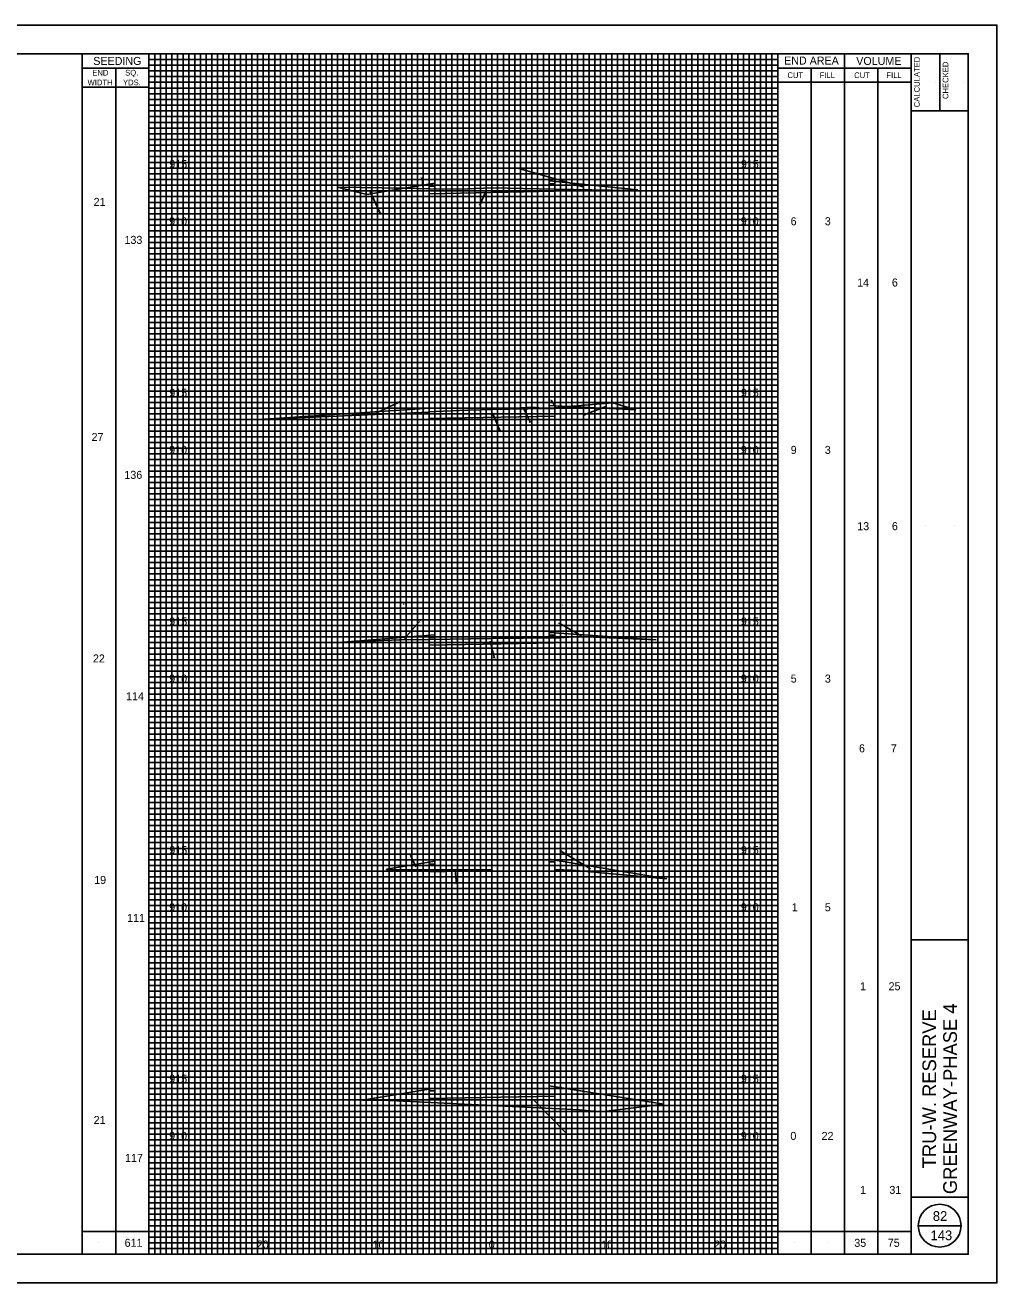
# Model space of a CAD drawing. Extents: x -73 to 160, y -2 to 1877.
# Drawn here: x 75 to 160, y 917.5 to 1027.5 of the extents above; entities that cross this region are included whole.
import ezdxf

# ---------------------------------------------------------------- set-up
doc = ezdxf.new("R2010")
doc.units = 0
for name, color, linetype in [('DR_P_Flood_Boundary', 7, 'Continuous'), ('GK_Cells', 7, 'Continuous'), ('RD_X_Fence', 7, 'Continuous'), ('TX_X_5', 7, 'Continuous'), ('UT_P_Water_Cells', 7, 'Continuous'), ('XS_P_Pavt_Layers', 7, 'Continuous'), ('XS_P_Pavt_Surface', 7, 'Continuous'), ('XS_X_Ground_Line', 7, 'Continuous')]:
    doc.layers.add(name, color=color, linetype=linetype)

msp = doc.modelspace()

# ---------------------------------------------------------------- linework, layer by layer
at = {"layer": 'DR_P_Flood_Boundary'}
for p, q in [((90.83, 920), (90.83, 1025)), ((95.83, 920), (95.83, 1025)), ((100.83, 920), (100.83, 1025)), ((105.83, 920), (105.83, 1025)), ((110.83, 920), (110.83, 1025)), ((115.83, 920), (115.83, 1025)), ((120.83, 920), (120.83, 1025)), ((125.83, 920), (125.83, 1025)), ((130.83, 920), (130.83, 1025)), ((135.83, 920), (135.83, 1025)), ((85.83, 1020), (140.83, 1020)), ((85.83, 1015), (140.83, 1015)), ((85.83, 1010), (140.83, 1010)), ((85.83, 1005), (140.83, 1005)), ((85.83, 1000), (140.83, 1000)), ((85.83, 995), (140.83, 995)), ((85.83, 990), (140.83, 990)), ((85.83, 985), (140.83, 985)), ((85.83, 980), (140.83, 980)), ((85.83, 975), (140.83, 975)), ((85.83, 970), (140.83, 970)), ((85.83, 965), (140.83, 965)), ((85.83, 960), (140.83, 960)), ((85.83, 955), (140.83, 955)), ((85.83, 950), (140.83, 950)), ((85.83, 945), (140.83, 945)), ((85.83, 940), (140.83, 940)), ((85.83, 935), (140.83, 935)), ((85.83, 930), (140.83, 930)), ((85.83, 925), (140.83, 925))]:
    msp.add_line(p, q, dxfattribs=at)
at = {"layer": 'GK_Cells'}
for p, q in [((152.5, 920), (152.5, 1025)), ((155, 1025), (155, 1020)), ((152.5, 1020), (157.5, 1020)), ((152.5, 947.5), (157.5, 947.5)), ((152.5, 925), (157.5, 925))]:
    msp.add_line(p, q, dxfattribs=at)
msp.add_lwpolyline([(0, 1025), (157.5, 1025), (157.5, 920), (0, 920)], close=True, dxfattribs=at)
at = {"layer": 'RD_X_Fence'}
for p, q in [((123.82, 1013.35), (118.29, 1014.94)), ((102.31, 1013.33), (104.88, 1012.69)), ((108.15, 1013.23), (102.31, 1013.33)), ((104.88, 1012.69), (108.15, 1013.23)), ((110.83, 1013.68), (108.15, 1013.23)), ((108.15, 1013.23), (110.33, 1013.19)), ((109.8, 1013.38), (109.72, 1014.17)), ((110.33, 1013.42), (110.83, 1013.43)), ((110.33, 1013.19), (110.33, 1013.42)), ((110.33, 1013.19), (110.33, 1012.75)), ((128.6, 1013.09), (120.83, 1013.88)), ((120.83, 1013.88), (120.83, 1013.77)), ((120.83, 1013.77), (120.83, 1013.63)), ((120.83, 1013.63), (121.33, 1013.64)), ((121.33, 1013.64), (121.33, 1013.16)), ((121.33, 1012.97), (121.33, 1013.16)), ((121.33, 1013.16), (127.83, 1013.04)), ((105.11, 1013.08), (106.05, 1011.06)), ((110.33, 1012.75), (121.33, 1012.97)), ((115.33, 1013.03), (114.78, 1011.77)), ((127.83, 1013.04), (128.6, 1013.09)), ((105.69, 993.57), (107.79, 994.55)), ((121.41, 994.12), (121, 994.71)), ((110.83, 994.02), (95.49, 993.02)), ((95.49, 993.02), (110.34, 993.64)), ((110.33, 993.68), (110.33, 993.09)), ((110.33, 993.09), (121.33, 993.31)), ((110.34, 993.68), (110.84, 993.7)), ((110.34, 993.64), (110.34, 993.68)), ((110.83, 993.92), (110.83, 994.02)), ((110.84, 993.7), (110.83, 993.92)), ((110.83, 993.92), (110.83, 993.92)), ((119.36, 994.09), (115.83, 993.87)), ((115.83, 993.87), (120.55, 993.96)), ((115.92, 993.53), (116.51, 992.04)), ((118.58, 993.97), (119.22, 992.76)), ((120.55, 993.96), (119.36, 994.09)), ((122.56, 994.14), (120.83, 994.22)), ((121.33, 993.31), (121.33, 993.98)), ((122.56, 994.14), (128.41, 993.86)), ((125.79, 994.15), (123.89, 993.41)), ((108.19, 973.86), (109.51, 975.34)), ((123.67, 974.08), (121.72, 975.2)), ((110.83, 974.19), (102.83, 973.54)), ((110.33, 973.93), (110.83, 973.94)), ((110.33, 973.77), (110.33, 973.93)), ((110.33, 973.77), (110.33, 973.26)), ((115.68, 973.61), (116.06, 972.15)), ((130.21, 973.75), (120.83, 974.39)), ((120.83, 974.39), (120.83, 974.29)), ((120.83, 974.29), (120.83, 974.14)), ((120.83, 974.14), (121.33, 974.15)), ((121.33, 974.15), (121.33, 973.92)), ((121.33, 973.48), (121.33, 973.92)), ((121.33, 973.92), (121.79, 973.92)), ((110.33, 973.26), (121.33, 973.48)), ((109.17, 953.88), (108.7, 954.9)), ((124.46, 953.71), (121.86, 955.25)), ((110.83, 954.37), (106.62, 953.67)), ((110.33, 954.11), (110.83, 954.12)), ((110.33, 953.65), (110.33, 954.11)), ((131.13, 952.85), (120.83, 954.57)), ((120.83, 954.32), (121.33, 954.33)), ((121.33, 954.33), (121.33, 953.66)), ((106.62, 953.64), (110.33, 953.61)), ((115.85, 953.62), (110.33, 953.65)), ((110.33, 953.65), (110.33, 953.44)), ((110.33, 953.44), (115.85, 953.55)), ((112.63, 953.56), (112.72, 952.41)), ((110.83, 934.54), (104.51, 933.49)), ((110.33, 934.28), (110.83, 934.29)), ((110.33, 933.61), (110.33, 934.28)), ((130.86, 933.13), (120.83, 934.74)), ((120.83, 934.49), (121.33, 934.5)), ((121.33, 934.5), (121.33, 933.83)), ((121.33, 933.83), (110.33, 933.61)), ((119.53, 933.44), (122.42, 930.49))]:
    msp.add_line(p, q, dxfattribs=at)
for points in [[(121.33, 1013.16), (115.83, 1013.27), (113.03, 1013.15), (110.33, 1013.19)], [(110.83, 1013.43), (110.83, 1013.57), (110.83, 1013.68)], [(128.41, 993.86), (126.4, 994.47), (125.69, 994.41), (122.56, 994.14)], [(113.72, 993.83), (110.84, 993.7), (110.34, 993.68), (110.33, 993.68)], [(110.83, 993.92), (110.83, 993.92)], [(121.33, 993.98), (120.83, 993.97), (120.55, 993.96), (115.83, 993.87), (113.72, 993.83)], [(120.83, 994.22), (120.83, 994.12), (120.83, 993.99)], [(120.83, 993.99), (121.33, 994.03), (122.56, 994.14)], [(102.83, 973.54), (107.75, 973.74), (110.33, 973.77)], [(121.33, 973.92), (115.83, 973.85), (110.33, 973.77)], [(110.83, 973.94), (110.83, 974.09), (110.83, 974.19)], [(121.79, 973.92), (123.34, 974.03), (130.21, 973.75)], [(110.83, 954.12), (110.83, 954.27), (110.83, 954.37)], [(120.83, 954.57), (120.83, 954.47), (120.83, 954.32)], [(106.62, 953.67), (106.62, 953.64)], [(110.33, 953.61), (110.33, 953.65)], [(115.85, 953.55), (115.85, 953.62)], [(121.33, 953.66), (121.33, 953.66)], [(121.33, 953.66), (122.86, 953.6), (131.13, 952.85)], [(110.83, 934.29), (110.83, 934.44), (110.83, 934.54)], [(120.83, 934.74), (120.83, 934.64), (120.83, 934.49)], [(104.51, 933.49), (106.31, 933.48), (115.83, 933.01), (123.48, 932.64), (125.36, 932.47), (130.86, 933.13)]]:
    msp.add_lwpolyline(points, dxfattribs=at)
at = {"layer": 'TX_X_5'}
msp.add_lwpolyline([(-10, 917.5), (160, 917.5), (160, 1027.5), (-10, 1027.5)], close=True, dxfattribs=at)
at = {"layer": 'UT_P_Water_Cells'}
for p, q in [((85.83, 1024.5), (140.83, 1024.5)), ((86.33, 920), (86.33, 1025)), ((86.83, 920), (86.83, 1025)), ((87.33, 920), (87.33, 1025)), ((87.83, 920), (87.83, 1025)), ((88.33, 920), (88.33, 1025)), ((88.83, 920), (88.83, 1025)), ((89.33, 920), (89.33, 1025)), ((89.83, 920), (89.83, 1025)), ((90.33, 920), (90.33, 1025)), ((91.33, 920), (91.33, 1025)), ((91.83, 920), (91.83, 1025)), ((92.33, 920), (92.33, 1025)), ((92.83, 920), (92.83, 1025)), ((93.33, 920), (93.33, 1025)), ((93.83, 920), (93.83, 1025)), ((94.33, 920), (94.33, 1025)), ((94.83, 920), (94.83, 1025)), ((95.33, 920), (95.33, 1025)), ((96.33, 920), (96.33, 1025)), ((96.83, 920), (96.83, 1025)), ((97.33, 920), (97.33, 1025)), ((97.83, 920), (97.83, 1025)), ((98.33, 920), (98.33, 1025)), ((98.83, 920), (98.83, 1025)), ((99.33, 920), (99.33, 1025)), ((99.83, 920), (99.83, 1025)), ((100.33, 920), (100.33, 1025)), ((101.33, 920), (101.33, 1025)), ((101.83, 920), (101.83, 1025)), ((102.33, 920), (102.33, 1025)), ((102.83, 920), (102.83, 1025)), ((103.33, 920), (103.33, 1025)), ((103.83, 920), (103.83, 1025)), ((104.33, 920), (104.33, 1025)), ((104.83, 920), (104.83, 1025)), ((105.33, 920), (105.33, 1025)), ((106.33, 920), (106.33, 1025)), ((106.83, 920), (106.83, 1025)), ((107.33, 920), (107.33, 1025)), ((107.83, 920), (107.83, 1025)), ((108.33, 920), (108.33, 1025)), ((108.83, 920), (108.83, 1025)), ((109.33, 920), (109.33, 1025)), ((109.83, 920), (109.83, 1025)), ((110.33, 920), (110.33, 1025)), ((111.33, 920), (111.33, 1025)), ((111.83, 920), (111.83, 1025)), ((112.33, 920), (112.33, 1025)), ((112.83, 920), (112.83, 1025)), ((113.33, 920), (113.33, 1025)), ((113.83, 920), (113.83, 1025)), ((114.33, 920), (114.33, 1025)), ((114.83, 920), (114.83, 1025)), ((115.33, 920), (115.33, 1025)), ((116.33, 920), (116.33, 1025)), ((116.83, 920), (116.83, 1025)), ((117.33, 920), (117.33, 1025)), ((117.83, 920), (117.83, 1025)), ((118.33, 920), (118.33, 1025)), ((118.83, 920), (118.83, 1025)), ((119.33, 920), (119.33, 1025)), ((119.83, 920), (119.83, 1025)), ((120.33, 920), (120.33, 1025)), ((121.33, 920), (121.33, 1025)), ((121.83, 920), (121.83, 1025)), ((122.33, 920), (122.33, 1025)), ((122.83, 920), (122.83, 1025)), ((123.33, 920), (123.33, 1025)), ((123.83, 920), (123.83, 1025)), ((124.33, 920), (124.33, 1025)), ((124.83, 920), (124.83, 1025)), ((125.33, 920), (125.33, 1025)), ((126.33, 920), (126.33, 1025)), ((126.83, 920), (126.83, 1025)), ((127.33, 920), (127.33, 1025)), ((127.83, 920), (127.83, 1025)), ((128.33, 920), (128.33, 1025)), ((128.83, 920), (128.83, 1025)), ((129.33, 920), (129.33, 1025)), ((129.83, 920), (129.83, 1025)), ((130.33, 920), (130.33, 1025)), ((131.33, 920), (131.33, 1025)), ((131.83, 920), (131.83, 1025)), ((132.33, 920), (132.33, 1025)), ((132.83, 920), (132.83, 1025)), ((133.33, 920), (133.33, 1025)), ((133.83, 920), (133.83, 1025)), ((134.33, 920), (134.33, 1025)), ((134.83, 920), (134.83, 1025)), ((135.33, 920), (135.33, 1025)), ((136.33, 920), (136.33, 1025)), ((136.83, 920), (136.83, 1025)), ((137.33, 920), (137.33, 1025)), ((137.83, 920), (137.83, 1025)), ((138.33, 920), (138.33, 1025)), ((138.83, 920), (138.83, 1025)), ((139.33, 920), (139.33, 1025)), ((139.83, 920), (139.83, 1025)), ((140.33, 920), (140.33, 1025)), ((85.83, 1024), (140.83, 1024)), ((85.83, 1023.5), (140.83, 1023.5)), ((85.83, 1023), (140.83, 1023)), ((85.83, 1022.5), (140.83, 1022.5)), ((85.83, 1022), (140.83, 1022)), ((85.83, 1021.5), (140.83, 1021.5)), ((85.83, 1021), (140.83, 1021)), ((85.83, 1020.5), (140.83, 1020.5)), ((85.83, 1019.5), (140.83, 1019.5)), ((85.83, 1019), (140.83, 1019)), ((85.83, 1018.5), (140.83, 1018.5)), ((85.83, 1018), (140.83, 1018)), ((85.83, 1017.5), (140.83, 1017.5)), ((85.83, 1017), (140.83, 1017)), ((85.83, 1016.5), (140.83, 1016.5)), ((85.83, 1016), (140.83, 1016)), ((85.83, 1015.5), (140.83, 1015.5)), ((85.83, 1014.5), (140.83, 1014.5)), ((85.83, 1014), (140.83, 1014)), ((85.83, 1013.5), (140.83, 1013.5)), ((85.83, 1013), (140.83, 1013)), ((85.83, 1012.5), (140.83, 1012.5)), ((85.83, 1012), (140.83, 1012)), ((85.83, 1011.5), (140.83, 1011.5)), ((85.83, 1011), (140.83, 1011)), ((85.83, 1010.5), (140.83, 1010.5)), ((85.83, 1009.5), (140.83, 1009.5)), ((85.83, 1009), (140.83, 1009)), ((85.83, 1008.5), (140.83, 1008.5)), ((85.83, 1008), (140.83, 1008)), ((85.83, 1007.5), (140.83, 1007.5)), ((85.83, 1007), (140.83, 1007)), ((85.83, 1006.5), (140.83, 1006.5)), ((85.83, 1006), (140.83, 1006)), ((85.83, 1005.5), (140.83, 1005.5)), ((85.83, 1004.5), (140.83, 1004.5)), ((85.83, 1004), (140.83, 1004)), ((85.83, 1003.5), (140.83, 1003.5)), ((85.83, 1003), (140.83, 1003)), ((85.83, 1002.5), (140.83, 1002.5)), ((85.83, 1002), (140.83, 1002)), ((85.83, 1001.5), (140.83, 1001.5)), ((85.83, 1001), (140.83, 1001)), ((85.83, 1000.5), (140.83, 1000.5)), ((85.83, 999.5), (140.83, 999.5)), ((85.83, 999), (140.83, 999)), ((85.83, 998.5), (140.83, 998.5)), ((85.83, 998), (140.83, 998)), ((85.83, 997.5), (140.83, 997.5)), ((85.83, 997), (140.83, 997)), ((85.83, 996.5), (140.83, 996.5)), ((85.83, 996), (140.83, 996)), ((85.83, 995.5), (140.83, 995.5)), ((85.83, 994.5), (140.83, 994.5)), ((85.83, 994), (140.83, 994)), ((85.83, 993.5), (140.83, 993.5)), ((85.83, 993), (140.83, 993)), ((85.83, 992.5), (140.83, 992.5)), ((85.83, 992), (140.83, 992)), ((85.83, 991.5), (140.83, 991.5)), ((85.83, 991), (140.83, 991)), ((85.83, 990.5), (140.83, 990.5)), ((85.83, 989.5), (140.83, 989.5)), ((85.83, 989), (140.83, 989)), ((85.83, 988.5), (140.83, 988.5)), ((85.83, 988), (140.83, 988)), ((85.83, 987.5), (140.83, 987.5)), ((85.83, 987), (140.83, 987)), ((85.83, 986.5), (140.83, 986.5)), ((85.83, 986), (140.83, 986)), ((85.83, 985.5), (140.83, 985.5)), ((85.83, 984.5), (140.83, 984.5)), ((85.83, 984), (140.83, 984)), ((85.83, 983.5), (140.83, 983.5)), ((85.83, 983), (140.83, 983)), ((85.83, 982.5), (140.83, 982.5)), ((85.83, 982), (140.83, 982)), ((85.83, 981.5), (140.83, 981.5)), ((85.83, 981), (140.83, 981)), ((85.83, 980.5), (140.83, 980.5)), ((85.83, 979.5), (140.83, 979.5)), ((85.83, 979), (140.83, 979)), ((85.83, 978.5), (140.83, 978.5)), ((85.83, 978), (140.83, 978)), ((85.83, 977.5), (140.83, 977.5)), ((85.83, 977), (140.83, 977)), ((85.83, 976.5), (140.83, 976.5)), ((85.83, 976), (140.83, 976)), ((85.83, 975.5), (140.83, 975.5)), ((85.83, 974.5), (140.83, 974.5)), ((85.83, 974), (140.83, 974)), ((85.83, 973.5), (140.83, 973.5)), ((85.83, 973), (140.83, 973)), ((85.83, 972.5), (140.83, 972.5)), ((85.83, 972), (140.83, 972)), ((85.83, 971.5), (140.83, 971.5)), ((85.83, 971), (140.83, 971)), ((85.83, 970.5), (140.83, 970.5)), ((85.83, 969.5), (140.83, 969.5)), ((85.83, 969), (140.83, 969)), ((85.83, 968.5), (140.83, 968.5)), ((85.83, 968), (140.83, 968)), ((85.83, 967.5), (140.83, 967.5)), ((85.83, 967), (140.83, 967)), ((85.83, 966.5), (140.83, 966.5)), ((85.83, 966), (140.83, 966)), ((85.83, 965.5), (140.83, 965.5)), ((85.83, 964.5), (140.83, 964.5)), ((85.83, 964), (140.83, 964)), ((85.83, 963.5), (140.83, 963.5)), ((85.83, 963), (140.83, 963)), ((85.83, 962.5), (140.83, 962.5)), ((85.83, 962), (140.83, 962)), ((85.83, 961.5), (140.83, 961.5)), ((85.83, 961), (140.83, 961)), ((85.83, 960.5), (140.83, 960.5)), ((85.83, 959.5), (140.83, 959.5)), ((85.83, 959), (140.83, 959)), ((85.83, 958.5), (140.83, 958.5)), ((85.83, 958), (140.83, 958)), ((85.83, 957.5), (140.83, 957.5)), ((85.83, 957), (140.83, 957)), ((85.83, 956.5), (140.83, 956.5)), ((85.83, 956), (140.83, 956)), ((85.83, 955.5), (140.83, 955.5)), ((85.83, 954.5), (140.83, 954.5)), ((85.83, 954), (140.83, 954)), ((85.83, 953.5), (140.83, 953.5)), ((85.83, 953), (140.83, 953)), ((85.83, 952.5), (140.83, 952.5)), ((85.83, 952), (140.83, 952)), ((85.83, 951.5), (140.83, 951.5)), ((85.83, 951), (140.83, 951)), ((85.83, 950.5), (140.83, 950.5)), ((85.83, 949.5), (140.83, 949.5)), ((85.83, 949), (140.83, 949)), ((85.83, 948.5), (140.83, 948.5)), ((85.83, 948), (140.83, 948)), ((85.83, 947.5), (140.83, 947.5)), ((85.83, 947), (140.83, 947)), ((85.83, 946.5), (140.83, 946.5)), ((85.83, 946), (140.83, 946)), ((85.83, 945.5), (140.83, 945.5)), ((85.83, 944.5), (140.83, 944.5)), ((85.83, 944), (140.83, 944)), ((85.83, 943.5), (140.83, 943.5)), ((85.83, 943), (140.83, 943)), ((85.83, 942.5), (140.83, 942.5)), ((85.83, 942), (140.83, 942)), ((85.83, 941.5), (140.83, 941.5)), ((85.83, 941), (140.83, 941)), ((85.83, 940.5), (140.83, 940.5)), ((85.83, 939.5), (140.83, 939.5)), ((85.83, 939), (140.83, 939)), ((85.83, 938.5), (140.83, 938.5)), ((85.83, 938), (140.83, 938)), ((85.83, 937.5), (140.83, 937.5)), ((85.83, 937), (140.83, 937)), ((85.83, 936.5), (140.83, 936.5)), ((85.83, 936), (140.83, 936)), ((85.83, 935.5), (140.83, 935.5)), ((85.83, 934.5), (140.83, 934.5)), ((85.83, 934), (140.83, 934)), ((85.83, 933.5), (140.83, 933.5)), ((85.83, 933), (140.83, 933)), ((85.83, 932.5), (140.83, 932.5)), ((85.83, 932), (140.83, 932)), ((85.83, 931.5), (140.83, 931.5)), ((85.83, 931), (140.83, 931)), ((85.83, 930.5), (140.83, 930.5)), ((85.83, 929.5), (140.83, 929.5)), ((85.83, 929), (140.83, 929)), ((85.83, 928.5), (140.83, 928.5)), ((85.83, 928), (140.83, 928)), ((85.83, 927.5), (140.83, 927.5)), ((85.83, 927), (140.83, 927)), ((85.83, 926.5), (140.83, 926.5)), ((85.83, 926), (140.83, 926)), ((85.83, 925.5), (140.83, 925.5)), ((85.83, 924.5), (140.83, 924.5)), ((85.83, 924), (140.83, 924)), ((85.83, 923.5), (140.83, 923.5)), ((85.83, 923), (140.83, 923)), ((85.83, 922.5), (140.83, 922.5)), ((85.83, 922), (140.83, 922)), ((85.83, 921.5), (140.83, 921.5)), ((85.83, 921), (140.83, 921)), ((85.83, 920.5), (140.83, 920.5))]:
    msp.add_line(p, q, dxfattribs=at)
at = {"layer": 'XS_X_Ground_Line'}
for p, q in [((80, 920), (80, 1025)), ((85.83, 920), (85.83, 1025)), ((140.83, 920), (140.83, 1025)), ((146.67, 920), (146.67, 1025)), ((85.83, 1023.75), (80, 1023.75)), ((82.92, 920), (82.92, 1023.75)), ((140.83, 1023.75), (152.5, 1023.75)), ((143.75, 920), (143.75, 1023.75)), ((149.58, 920), (149.58, 1023.75)), ((85.83, 1022.08), (80, 1022.08)), ((140.83, 1022.5), (152.5, 1022.5)), ((154.6, 1022.52), (154.6, 1022.52)), ((157.1, 1022.52), (157.1, 1022.52)), ((153.75, 983.75), (153.75, 983.75)), ((156.26, 983.75), (156.26, 983.75)), ((155, 936.46), (155, 936.46)), ((155, 922.92), (155, 922.92)), ((80, 922), (85.83, 922)), ((140.83, 922), (152.5, 922)), ((153.12, 922.5), (156.88, 922.5)), ((81.46, 921.03), (81.46, 921.03)), ((84.37, 921.03), (84.37, 921.03)), ((142.29, 921), (142.29, 921)), ((145.21, 921), (145.21, 921)), ((148.12, 921), (148.12, 921)), ((151.04, 921), (151.04, 921)), ((155, 921.23), (155, 921.23))]:
    msp.add_line(p, q, dxfattribs=at)
msp.add_circle((155, 922.5), 1.87, dxfattribs=at)

# ---------------------------------------------------------------- texts
at = {"layer": 'RD_X_Fence'}
for s, p in [('7.8', (122.64, 1016.4)), ('2.7', (103.42, 1015.86)), ('6.0', (106.56, 1015.69)), ('0.5', (109.57, 1014.1)), ('2.7', (118.14, 1014.87)), ('1.8', (105.93, 1010.99)), ('3.8', (114.63, 1011.7)), ('15.4', (109.19, 997.4)), ('7.6', (123.24, 996.95)), ('2.7', (107.64, 994.48)), ('0.2', (120.84, 994.64)), ('1.5', (123.77, 993.34)), ('0.3', (119.07, 992.69)), ('7.2', (116.37, 991.97)), ('8.0', (108.04, 976.79)), ('9.4', (121.8, 976.69)), ('1.3', (109.39, 975.27)), ('1.4', (121.6, 975.13)), ('5.2', (115.92, 972.08)), ('4.3', (109.62, 956.22)), ('10.4', (123, 956.09)), ('1.4', (108.58, 954.83)), ('3.8', (121.71, 955.18)), ('0.8', (112.57, 952.34)), ('10.2', (122.59, 938.32)), ('6.4', (109.13, 937.75)), ('22.4', (122.22, 930.42))]:
    msp.add_text(s, height=0.14, dxfattribs=at).set_placement(p)
at = {"layer": 'XS_P_Pavt_Layers'}
for s, p in [('82', (154.4, 922.92)), ('143', (154.2, 921.23))]:
    msp.add_text(s, height=0.85, dxfattribs=at).set_placement(p)
at = {"layer": 'XS_P_Pavt_Surface'}
for s, p in [('915', (87.61, 1015)), ('915', (137.61, 1015)), ('21', (80.99, 1011.69)), ('910', (87.6, 1010)), ('910', (137.6, 1010)), ('6', (141.96, 1010)), ('3', (144.95, 1010)), ('133', (83.69, 1008.37)), ('14', (147.78, 1004.64)), ('6', (150.82, 1004.64)), ('915', (87.61, 995)), ('915', (137.61, 995)), ('27', (80.81, 991.13)), ('910', (87.6, 990)), ('910', (137.6, 990)), ('9', (141.97, 990)), ('3', (144.95, 990)), ('136', (83.68, 987.82)), ('13', (147.79, 983.33)), ('6', (150.82, 983.33)), ('915', (87.61, 975)), ('915', (137.61, 975)), ('22', (80.93, 971.76)), ('910', (87.6, 970)), ('910', (137.6, 970)), ('5', (141.97, 970)), ('3', (144.95, 970)), ('114', (83.83, 968.45)), ('6', (147.94, 963.9)), ('7', (150.73, 963.9)), ('915', (87.61, 955)), ('915', (137.61, 955)), ('19', (81.04, 952.39)), ('910', (87.6, 950)), ('910', (137.6, 950)), ('1', (142.06, 950)), ('5', (144.95, 950)), ('111', (83.92, 949.07)), ('1', (148.04, 943.09)), ('25', (150.53, 943.09)), ('915', (87.61, 935)), ('915', (137.61, 935)), ('21', (80.99, 931.39)), ('910', (87.6, 930)), ('910', (137.6, 930)), ('0', (141.94, 930)), ('22', (144.67, 930)), ('117', (83.74, 928.08)), ('1', (148.04, 925.28)), ('31', (150.6, 925.28)), ('611', (83.7, 920.65)), ('20', (95.26, 920.5)), ('10', (105.39, 920.5)), ('0', (115.55, 920.5)), ('0', (115.55, 920.5)), ('10', (125.39, 920.5)), ('20', (135.26, 920.5)), ('35', (147.53, 920.65)), ('75', (150.46, 920.65))]:
    msp.add_text(s, height=0.7, dxfattribs=at).set_placement(p)
for s, p in [('GREENWAY-PHASE 4', (156.51, 925.26)), ('TRU-W. RESERVE', (154.69, 927.52))]:
    msp.add_text(s, height=1.2, rotation=90, dxfattribs=at).set_placement(p)
at = {"layer": 'XS_X_Ground_Line'}
for s, height, p in [('SEEDING', 0.7, (80.96, 1024.02)), ('END AREA', 0.7, (141.39, 1024.05)), ('VOLUME', 0.7, (147.7, 1024.02)), ('END', 0.5, (80.87, 1023.09)), ('SQ.', 0.5, (83.75, 1023.09)), ('CUT', 0.5, (141.68, 1022.87)), ('FILL', 0.5, (144.5, 1022.87)), ('CUT', 0.5, (147.52, 1022.87)), ('FILL', 0.5, (150.34, 1022.87)), ('WIDTH', 0.5, (80.46, 1022.24)), ('YDS.', 0.5, (83.56, 1022.24)), ('143', 0.85, (154.2, 921.23))]:
    msp.add_text(s, height=height, dxfattribs=at).set_placement(p)
for s, p in [('CALCULATED', (153.26, 1020.32)), ('CHECKED', (155.76, 1021.04))]:
    msp.add_text(s, height=0.5, rotation=90, dxfattribs=at).set_placement(p)

doc.saveas('drawing.dxf')
